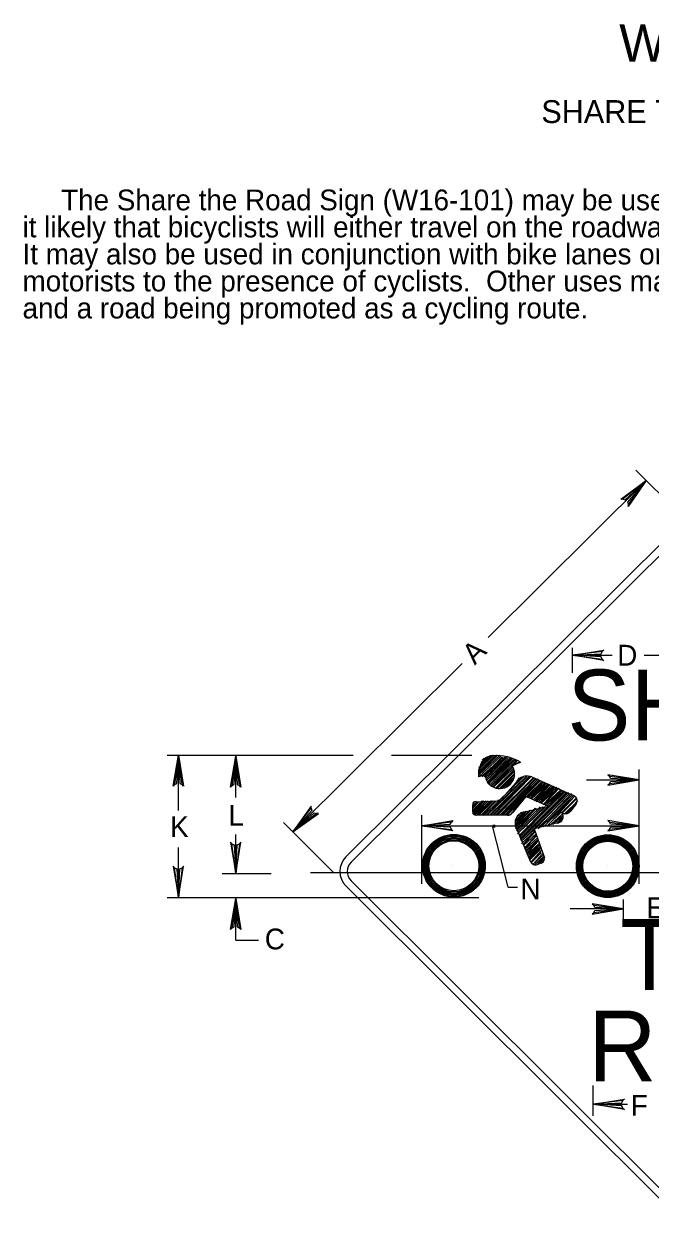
# Model space of a CAD drawing. Extents: x 0.012 to 0.188, y 0.004 to 0.259.
# Drawn here: x 0.0263 to 0.1016, y 0.1165 to 0.2592 of the extents above; entities that cross this region are included whole.
import ezdxf

# ---------------------------------------------------------------- set-up
doc = ezdxf.new("R2010")
doc.units = 0
for name, color, linetype in [('1', 7, 'Continuous'), ('12', 7, 'Continuous'), ('2', 7, 'Continuous'), ('3', 7, 'Continuous')]:
    doc.layers.add(name, color=color, linetype=linetype)

# ---------------------------------------------------------------- blocks, each defined once
blk = doc.blocks.new('RARROW')
at = {"layer": '3'}
for p, q in [((-2.156, 0.28500000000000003), (-2.2665, 0.384625)), ((-2.2665, 0.384625), (0, 0)), ((0, 0), (-2.2665, -0.379125)), ((-2.156, 0.28500000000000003), (-2.075625, 0.12075)), ((0, 0), (-2.156, 0.28500000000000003)), ((-2.14975, -0.2705), (0, 0)), ((-2.075625, 0.12075), (0, 0)), ((0, 0), (-2.074, -0.108)), ((-2.2665, -0.379125), (-2.14975, -0.2705)), ((-2.074, -0.108), (-2.14975, -0.2705))]:
    blk.add_line(p, q, dxfattribs=at)

msp = doc.modelspace()

# ---------------------------------------------------------------- linework, layer by layer
at = {"layer": '1'}
for p, q in [((0.099875, 0.20550000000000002), (0.10525, 0.200125)), ((0.082125, 0.185375), (0.101125, 0.20425000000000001)), ((0.059000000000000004, 0.162375), (0.079, 0.18225)), ((0.043500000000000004, 0.17125), (0.065875, 0.17125)), ((0.044875, 0.16459030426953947), (0.044875, 0.17125)), ((0.07050000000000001, 0.17125), (0.080125, 0.17125)), ((0.051750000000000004, 0.1661307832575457), (0.051750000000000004, 0.171125)), ((0.0575, 0.163125), (0.0635, 0.15712500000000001)), ((0.074125, 0.15575), (0.074125, 0.164)), ((0.074125, 0.16275), (0.10025, 0.16275)), ((0.051750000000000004, 0.157), (0.051750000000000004, 0.16170685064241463)), ((0.044875, 0.154125), (0.044875, 0.16011432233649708)), ((0.050125, 0.157), (0.056, 0.157)), ((0.06075, 0.15712500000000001), (0.15075, 0.15712500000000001)), ((0.043500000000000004, 0.154125), (0.081, 0.154125)), ((0.051750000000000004, 0.149), (0.051750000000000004, 0.154125)), ((0.051750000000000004, 0.149), (0.0545, 0.149))]:
    msp.add_line(p, q, dxfattribs=at)
at = {"layer": '12'}
for p, q in [((0.065, 0.159), (0.104125, 0.197875)), ((0.065625, 0.15837500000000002), (0.10475, 0.19725)), ((0.09225, 0.181125), (0.09225, 0.184125)), ((0.09225, 0.18325), (0.097, 0.18325)), ((0.100875, 0.18325), (0.10575, 0.18325)), ((0.081, 0.169625), (0.082625, 0.17125)), ((0.081, 0.1695), (0.08275, 0.17125)), ((0.081, 0.16925), (0.083, 0.17125)), ((0.081, 0.169125), (0.083125, 0.17125)), ((0.081, 0.169), (0.08325, 0.17125)), ((0.081, 0.168875), (0.0835, 0.17125)), ((0.081, 0.16975), (0.082375, 0.171125)), ((0.081, 0.168625), (0.083625, 0.171125)), ((0.08125, 0.170125), (0.082125, 0.171)), ((0.08125, 0.170375), (0.081875, 0.170875)), ((0.081375, 0.168625), (0.08375, 0.171)), ((0.081375, 0.170625), (0.081625, 0.170875)), ((0.0815, 0.168875), (0.083875, 0.171)), ((0.081625, 0.168875), (0.084125, 0.171)), ((0.081625, 0.168625), (0.08425, 0.171)), ((0.08175, 0.1685), (0.084375, 0.171)), ((0.081875, 0.168375), (0.084375, 0.171)), ((0.081875, 0.168125), (0.0845, 0.170875)), ((0.081875, 0.168125), (0.08475, 0.170875)), ((0.082, 0.168), (0.084875, 0.170875)), ((0.082, 0.167875), (0.085, 0.170875)), ((0.082125, 0.167875), (0.085, 0.17075)), ((0.082125, 0.16775), (0.08525, 0.17075)), ((0.082375, 0.16775), (0.085375, 0.17075)), ((0.082375, 0.1675), (0.0855, 0.170625)), ((0.0825, 0.1675), (0.085, 0.169875)), ((0.082625, 0.167375), (0.085, 0.169875)), ((0.08600000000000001, 0.170375), (0.084875, 0.169875)), ((0.085, 0.17), (0.0855, 0.170625)), ((0.08525, 0.170125), (0.085625, 0.170625)), ((0.0855, 0.17025), (0.085875, 0.170375)), ((0.085875, 0.170375), (0.08600000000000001, 0.170375)), ((0.085875, 0.17025), (0.085875, 0.170375)), ((0.081, 0.168625), (0.081, 0.1695)), ((0.081625, 0.168875), (0.081, 0.168625)), ((0.081625, 0.164), (0.08637500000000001, 0.168625)), ((0.081875, 0.164), (0.08662500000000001, 0.168625)), ((0.082, 0.164), (0.08675000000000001, 0.168625)), ((0.08225, 0.164), (0.08700000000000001, 0.168625)), ((0.082375, 0.164), (0.08712500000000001, 0.168625)), ((0.082625, 0.167375), (0.085, 0.16975)), ((0.082625, 0.164), (0.08725000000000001, 0.168625)), ((0.08275, 0.167375), (0.085125, 0.169625)), ((0.08275, 0.164), (0.08725000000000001, 0.168625)), ((0.083, 0.16725), (0.08525, 0.1695)), ((0.083, 0.164), (0.08750000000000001, 0.1685)), ((0.083125, 0.16725), (0.08525, 0.169375)), ((0.083125, 0.164), (0.08762500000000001, 0.1685)), ((0.08325, 0.16725), (0.08525, 0.16925)), ((0.08325, 0.164), (0.08762500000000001, 0.1685)), ((0.0835, 0.16725), (0.08525, 0.169)), ((0.083625, 0.16725), (0.08525, 0.168875)), ((0.08375, 0.16725), (0.08525, 0.168625)), ((0.083875, 0.16725), (0.08525, 0.1685)), ((0.08475, 0.167), (0.08612500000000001, 0.1685)), ((0.0855, 0.168), (0.085875, 0.1685)), ((0.08737500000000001, 0.168625), (0.092375, 0.166375)), ((0.10025, 0.15575), (0.10025, 0.1695)), ((0.0835, 0.164), (0.08775000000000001, 0.168375)), ((0.083625, 0.164), (0.08787500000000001, 0.168375)), ((0.08375, 0.164), (0.088125, 0.168375)), ((0.08375, 0.166), (0.08575, 0.16825)), ((0.083875, 0.164), (0.088125, 0.168125)), ((0.084125, 0.164), (0.08825, 0.168125)), ((0.08425, 0.167375), (0.085, 0.168125)), ((0.08425, 0.164), (0.088375, 0.168125)), ((0.084375, 0.164), (0.0885, 0.168)), ((0.08675000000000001, 0.166125), (0.088625, 0.168)), ((0.08687500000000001, 0.166125), (0.08875, 0.168)), ((0.08700000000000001, 0.166125), (0.088875, 0.167875)), ((0.08712500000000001, 0.166), (0.089, 0.167875)), ((0.08725000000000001, 0.166), (0.089125, 0.167875)), ((0.08737500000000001, 0.166), (0.08925, 0.16775)), ((0.08750000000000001, 0.165875), (0.089375, 0.16775)), ((0.08762500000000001, 0.16575), (0.0895, 0.16775)), ((0.08775000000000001, 0.16575), (0.0895, 0.167625)), ((0.08787500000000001, 0.16575), (0.089625, 0.1675)), ((0.08787500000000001, 0.165625), (0.089875, 0.1675)), ((0.088125, 0.165625), (0.09, 0.1675)), ((0.08825, 0.1655), (0.09, 0.167375)), ((0.088375, 0.1655), (0.090125, 0.167375)), ((0.088375, 0.1655), (0.090375, 0.167375)), ((0.0885, 0.1655), (0.0905, 0.16725)), ((0.08875, 0.16525), (0.0905, 0.16725)), ((0.08875, 0.16525), (0.090625, 0.16725)), ((0.088875, 0.16525), (0.09075, 0.167)), ((0.089, 0.165125), (0.090875, 0.167)), ((0.08925, 0.165125), (0.091, 0.167)), ((0.09393189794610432, 0.16825), (0.10025, 0.16825)), ((0.08025, 0.1645), (0.081375, 0.16575)), ((0.08025, 0.164375), (0.0815, 0.16575)), ((0.08025, 0.164125), (0.081625, 0.16575)), ((0.08025, 0.1655), (0.080375, 0.165625)), ((0.08025, 0.165125), (0.08075, 0.165625)), ((0.08025, 0.165), (0.080875, 0.165625)), ((0.08025, 0.164875), (0.081, 0.165625)), ((0.08025, 0.164625), (0.08125, 0.165625)), ((0.080375, 0.164125), (0.081875, 0.16575)), ((0.080375, 0.164), (0.082125, 0.16575)), ((0.0805, 0.164), (0.082375, 0.16575)), ((0.080625, 0.165625), (0.08325, 0.16575)), ((0.08075, 0.164), (0.0825, 0.16575)), ((0.08075, 0.165625), (0.08075, 0.165625)), ((0.080875, 0.164), (0.082625, 0.16575)), ((0.081, 0.164), (0.08275, 0.16575)), ((0.08125, 0.164), (0.083, 0.16575)), ((0.081375, 0.164), (0.083125, 0.16575)), ((0.0815, 0.164), (0.0835, 0.16575)), ((0.08662500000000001, 0.16625), (0.085, 0.16425)), ((0.08600000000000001, 0.16125), (0.0915, 0.16675)), ((0.08600000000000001, 0.161125), (0.091625, 0.16675)), ((0.08600000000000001, 0.161), (0.09175, 0.16675)), ((0.08612500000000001, 0.160875), (0.091875, 0.166625)), ((0.08662500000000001, 0.16625), (0.08662500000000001, 0.16625)), ((0.08662500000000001, 0.16625), (0.08662500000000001, 0.16625)), ((0.0895, 0.165), (0.08662500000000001, 0.16625)), ((0.08775000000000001, 0.162375), (0.091875, 0.166625)), ((0.088125, 0.162375), (0.092125, 0.166625)), ((0.08825, 0.162625), (0.09225, 0.1665)), ((0.0885, 0.162625), (0.092375, 0.166375)), ((0.08875, 0.162625), (0.092375, 0.166375)), ((0.088875, 0.16275), (0.0925, 0.16625)), ((0.08925, 0.165125), (0.091125, 0.166875)), ((0.08925, 0.16275), (0.0925, 0.16625)), ((0.089375, 0.165), (0.09125, 0.166875)), ((0.0895, 0.165), (0.091375, 0.166875)), ((0.091, 0.164375), (0.09275, 0.166125)), ((0.091, 0.164375), (0.09275, 0.166125)), ((0.091125, 0.164375), (0.09275, 0.166)), ((0.09125, 0.164125), (0.092875, 0.16575)), ((0.0915, 0.164125), (0.09275, 0.165625)), ((0.08025, 0.1645), (0.08025, 0.165125)), ((0.08475, 0.164), (0.085625, 0.165)), ((0.084875, 0.164125), (0.084875, 0.164125)), ((0.085375, 0.162375), (0.08775000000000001, 0.164875)), ((0.085375, 0.162875), (0.08712500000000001, 0.164625)), ((0.085375, 0.16275), (0.08725000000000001, 0.164625)), ((0.085375, 0.162625), (0.08750000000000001, 0.164625)), ((0.085375, 0.16325), (0.08662500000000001, 0.1645)), ((0.085375, 0.163), (0.08675000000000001, 0.1645)), ((0.085375, 0.163375), (0.08637500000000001, 0.164375)), ((0.0855, 0.162125), (0.088375, 0.165)), ((0.0855, 0.16225), (0.08787500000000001, 0.164875)), ((0.0855, 0.16225), (0.08825, 0.164875)), ((0.0855, 0.16375), (0.08612500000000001, 0.164375)), ((0.085625, 0.162), (0.088625, 0.165)), ((0.085625, 0.16175), (0.088875, 0.165)), ((0.085625, 0.16175), (0.089, 0.165)), ((0.085875, 0.161625), (0.08925, 0.165)), ((0.085875, 0.1615), (0.089375, 0.165)), ((0.085875, 0.161375), (0.0895, 0.165)), ((0.08637500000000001, 0.164375), (0.088375, 0.164875)), ((0.08925, 0.165125), (0.08925, 0.165125)), ((0.089375, 0.162875), (0.090875, 0.164375)), ((0.089625, 0.162875), (0.091, 0.164125)), ((0.089875, 0.162875), (0.091, 0.164125)), ((0.091125, 0.16425), (0.090875, 0.164375)), ((0.09175, 0.164375), (0.092375, 0.165)), ((0.092625, 0.16525), (0.092, 0.1645)), ((0.084375, 0.164), (0.08075, 0.164)), ((0.0845, 0.155375), (0.082625, 0.16275)), ((0.090625, 0.163125), (0.08762500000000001, 0.162375)), ((0.09, 0.163), (0.091125, 0.164)), ((0.090375, 0.163), (0.091125, 0.163875)), ((0.0905, 0.163), (0.091125, 0.16375)), ((0.090625, 0.16325), (0.091, 0.1635)), ((0.090625, 0.16325), (0.091, 0.1635)), ((0.09075, 0.16325), (0.091, 0.163375)), ((0.08725000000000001, 0.15837500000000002), (0.0855, 0.1625)), ((0.08612500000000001, 0.160875), (0.08762500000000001, 0.16225)), ((0.08612500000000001, 0.160625), (0.08775000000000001, 0.162125)), ((0.08637500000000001, 0.1605), (0.08775000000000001, 0.162125)), ((0.08637500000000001, 0.1605), (0.08775000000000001, 0.162)), ((0.08637500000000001, 0.160375), (0.08787500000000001, 0.16175)), ((0.08650000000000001, 0.160125), (0.08787500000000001, 0.161625)), ((0.08650000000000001, 0.16), (0.08787500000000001, 0.1615)), ((0.08650000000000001, 0.16), (0.08787500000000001, 0.1615)), ((0.08650000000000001, 0.15987500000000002), (0.088, 0.16125)), ((0.08762500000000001, 0.162375), (0.088875, 0.15887500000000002)), ((0.08662500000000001, 0.15975), (0.088125, 0.161125)), ((0.08662500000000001, 0.15962500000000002), (0.088125, 0.161)), ((0.08675000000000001, 0.1595), (0.088125, 0.160875)), ((0.08675000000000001, 0.15937500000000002), (0.088125, 0.160875)), ((0.08675000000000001, 0.15925), (0.08825, 0.160625)), ((0.08687500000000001, 0.15912500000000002), (0.08825, 0.1605)), ((0.08700000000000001, 0.159), (0.08825, 0.160375)), ((0.08700000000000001, 0.15887500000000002), (0.088375, 0.16025)), ((0.08700000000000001, 0.15875), (0.088375, 0.160125)), ((0.08712500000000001, 0.15875), (0.088375, 0.16)), ((0.08712500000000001, 0.15862500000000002), (0.088375, 0.15987500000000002)), ((0.08725000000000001, 0.15837500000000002), (0.0885, 0.15975)), ((0.08725000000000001, 0.15825), (0.0885, 0.15962500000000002)), ((0.08725000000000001, 0.15825), (0.0885, 0.1595)), ((0.08750000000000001, 0.15812500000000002), (0.088625, 0.15937500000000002)), ((0.08750000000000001, 0.15812500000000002), (0.08875, 0.15925)), ((0.08762500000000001, 0.158), (0.08875, 0.159)), ((0.08775000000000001, 0.15812500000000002), (0.08875, 0.159)), ((0.088125, 0.15812500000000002), (0.08875, 0.15887500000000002)), ((0.088375, 0.15825), (0.088875, 0.15875)), ((0.077875, 0.158), (0.077875, 0.158)), ((0.08750000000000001, 0.158), (0.08750000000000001, 0.158)), ((0.0885, 0.15825), (0.08787500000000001, 0.158)), ((0.0885, 0.15825), (0.08875, 0.15837500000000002)), ((0.0885, 0.15825), (0.0885, 0.15825)), ((0.08875, 0.15837500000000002), (0.08875, 0.15837500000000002)), ((0.0965, 0.158), (0.0965, 0.158)), ((0.10475, 0.117125), (0.065625, 0.156125)), ((0.104125, 0.1165), (0.065, 0.1555)), ((0.0845, 0.155375), (0.085625, 0.155375)), ((0.098375, 0.15275), (0.09198443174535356, 0.15275)), ((0.098375, 0.151375), (0.098375, 0.153875)), ((0.09475, 0.12787500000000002), (0.09475, 0.1315)), ((0.09475, 0.12925), (0.098875, 0.12925))]:
    msp.add_line(p, q, dxfattribs=at)
for centre, radius in [((0.07798326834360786, 0.15792617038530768), 0.0037659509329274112), ((0.0779832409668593, 0.15792611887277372), 0.0036536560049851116), ((0.0779832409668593, 0.15792611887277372), 0.00353950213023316), ((0.0779832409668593, 0.15792611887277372), 0.003398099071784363), ((0.09649173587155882, 0.15789937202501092), 0.0037659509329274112), ((0.09649210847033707, 0.15787212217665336), 0.003763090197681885), ((0.09649210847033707, 0.15787212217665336), 0.003677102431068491), ((0.09649210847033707, 0.15787212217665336), 0.0035619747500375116), ((0.09649210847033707, 0.15787212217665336), 0.0034488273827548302), ((0.0779832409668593, 0.15792611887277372), 0.0032824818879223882), ((0.0779832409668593, 0.15792611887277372), 0.0031400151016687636), ((0.0779832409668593, 0.15792611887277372), 0.0030100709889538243), ((0.09649210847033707, 0.15787212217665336), 0.003364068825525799), ((0.09649210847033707, 0.15787212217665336), 0.003279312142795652), ((0.09649210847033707, 0.15787212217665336), 0.0031649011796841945), ((0.09649210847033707, 0.15787212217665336), 0.0030794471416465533), ((0.09649210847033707, 0.15787212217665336), 0.0030100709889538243)]:
    msp.add_circle(centre, radius, dxfattribs=at)
for centre, radius, start, end in [((0.08268212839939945, 0.16959673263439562), 0.0015707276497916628, 88.48155, 184.50301666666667), ((0.08350835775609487, 0.16899599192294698), 0.0017806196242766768, 184.73358055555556, 34.57944444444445), ((0.08309165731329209, 0.16544735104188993), 0.005731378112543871, 59.344427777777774, 93.68043888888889), ((0.08678809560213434, 0.1672858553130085), 0.0014399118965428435, 66.67193611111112, 137.9205527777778), ((0.08070427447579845, 0.16518538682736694), 0.00047997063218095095, 93.07155277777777, 180), ((0.08318685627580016, 0.16652025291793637), 0.0007199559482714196, 273.0687638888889, 317.92113333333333), ((0.0920968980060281, 0.16572292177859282), 0.0007089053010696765, 318.1551694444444, 66.90245), ((0.08070427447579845, 0.16449571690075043), 0.00047997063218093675, 180, 270), ((0.08443589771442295, 0.16473570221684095), 0.0007199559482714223, 270, 318.1571388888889), ((0.08677454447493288, 0.16302653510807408), 0.001439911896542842, 104.30228055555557, 204.00179722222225), ((0.08923622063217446, 0.16259054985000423), 0.002423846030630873, 83.75231111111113, 110.81254444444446), ((0.09042201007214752, 0.16381960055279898), 0.0007236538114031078, 286.2904638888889, 47.503113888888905), ((0.0913879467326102, 0.1649859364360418), 0.0007815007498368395, 250.33842222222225, 321.5523694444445), ((0.06674999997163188, 0.15725000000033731), 0.002474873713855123, 135.00000000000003, 225.00000000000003), ((0.08838286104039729, 0.15873673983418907), 0.00047997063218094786, 288.85433611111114, 18.41683888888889), ((0.06674999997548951, 0.1572500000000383), 0.0015909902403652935, 135.00000000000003, 225.00000000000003), ((0.08773274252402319, 0.15851476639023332), 0.0004799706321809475, 203.99310277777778, 288.8420277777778)]:
    msp.add_arc(centre, radius, start, end, dxfattribs=at)

# ---------------------------------------------------------------- block references
at = {"layer": '3'}
for p, xscale, yscale, rotation in [((0.101125, 0.20425000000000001), 0.0016545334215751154, 0.0016366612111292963, 45.86895778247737), ((0.09225, 0.18325), 0.0016545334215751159, 0.0016366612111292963, 180), ((0.044875, 0.17125), 0.0016545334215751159, 0.0016366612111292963, 90), ((0.051750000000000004, 0.171125), 0.0016545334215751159, 0.0016366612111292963, 90), ((0.058625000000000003, 0.162), 0.0016545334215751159, -0.0016366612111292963, -135.02896890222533), ((0.074125, 0.16275), 0.0016545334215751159, 0.0016366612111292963, 180), ((0.051750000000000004, 0.157), 0.0016545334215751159, -0.0016366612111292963, -90), ((0.044875, 0.154125), 0.0016545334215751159, -0.0016366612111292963, -90), ((0.051750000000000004, 0.154), 0.0016545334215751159, 0.0016366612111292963, 90), ((0.09475, 0.12925), 0.0016545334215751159, 0.0016366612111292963, 180)]:
    msp.add_blockref('RARROW', p, dxfattribs=dict(at, xscale=xscale, yscale=yscale, rotation=rotation))
at = {"layer": '3', "xscale": 0.0016545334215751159, "yscale": -0.0016366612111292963}
for p in [(0.10025, 0.16825), (0.10025, 0.16275), (0.098375, 0.15275)]:
    msp.add_blockref('RARROW', p, dxfattribs=at)

# ---------------------------------------------------------------- texts
at = {"layer": '1'}
for s, height, p in [('W16-101', 0.0045000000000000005, (0.09786363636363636, 0.254625)), ('SHARE THE ROAD SIGN', 0.00275025, (0.0885, 0.24725)), ('L', 0.0024997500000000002, (0.050875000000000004, 0.16275)), ('K', 0.0024997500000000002, (0.043875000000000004, 0.161375)), ('C', 0.0024997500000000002, (0.05525, 0.147875))]:
    msp.add_text(s, height=height, dxfattribs=at).set_placement(p)
msp.add_text('A', height=0.0024997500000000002, rotation=45, dxfattribs=at).set_placement((0.0805, 0.182))
at = {"layer": '12'}
for s, height, p in [('D', 0.0024997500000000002, (0.097625, 0.182)), ('SHARE', 0.008517, (0.091625, 0.17300000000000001)), ('.', 0.00239925, (0.082375, 0.1625)), ('N', 0.0024997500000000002, (0.08600000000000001, 0.153875)), ('E', 0.0024997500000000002, (0.101125, 0.151625)), ('THE', 0.008517, (0.098, 0.14300000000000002)), ('ROAD', 0.008517, (0.094125, 0.132)), ('F', 0.0024997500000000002, (0.09925, 0.12787500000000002))]:
    msp.add_text(s, height=height, dxfattribs=at).set_placement(p)
at = {"layer": '2'}
for s, p in [('     The Share the Road Sign (W16-101) may be used on highways where available lateral clearances make', (0.026125, 0.23674962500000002)), ('it likely that bicyclists will either travel on the roadway or on the shoulder but in close proximity to the roadway.', (0.026125, 0.233499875)), ('It may also be used in conjunction with bike lanes or roads with wide paved shoulders if the intent is to alert ', (0.026125, 0.230250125)), ('motorists to the presence of cyclists.  Other uses may include roads with a documented car-bike crash history', (0.026125, 0.227000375)), ('and a road being promoted as a cycling route.', (0.026125, 0.223750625))]:
    msp.add_text(s, height=0.0024997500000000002, dxfattribs=at).set_placement(p)

doc.saveas('drawing.dxf')
